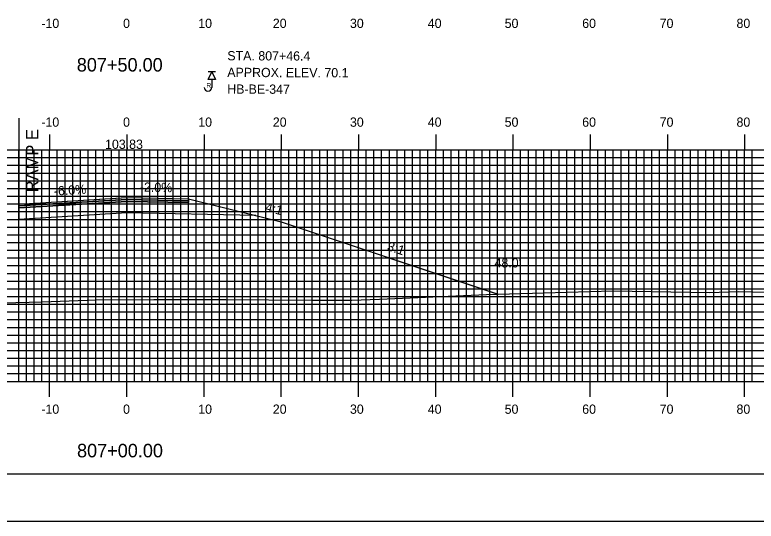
# Model space of a CAD drawing. Extents: x 1272 to 1616, y -1658 to -1438.
# Drawn here: x 1423.7 to 1519.7, y -1657.7 to -1592.1 of the extents above; entities that cross this region are included whole.
import ezdxf

# ---------------------------------------------------------------- set-up
doc = ezdxf.new("R2010")
doc.units = 0
for name, color, linetype in [('ANNOTATION', 7, 'Continuous'), ('BORDER', 7, 'Continuous'), ('BORING - REFUSAL', 7, 'Continuous'), ('D_Roadway_Centerline', 7, 'Continuous'), ('D_Roadway_Centerline_Text', 7, 'Continuous'), ('D_Roadway_Edge_Shoulder', 7, 'Continuous'), ('D_Roadway_Edge_TW', 7, 'Continuous'), ('D_Roadway_Pavement', 7, 'Continuous'), ('D_Roadway_SlopeLines', 7, 'Continuous'), ('D_Roadway_SubGrade', 7, 'Continuous'), ('D_Text_Standard', 7, 'Continuous'), ('H_V ANNOTATION', 7, 'Continuous'), ('MAJOR', 7, 'Continuous'), ('MINOR', 7, 'Continuous'), ('PLOT BOUNDARY', 7, 'Continuous'), ('S_Roadway_Centerline', 7, 'Continuous')]:
    doc.layers.add(name, color=color, linetype=linetype)

msp = doc.modelspace()

# ---------------------------------------------------------------- linework, layer by layer
at = {"layer": 'BORDER'}
msp.add_lwpolyline([(1288.561, -1651.604), (1608.561, -1651.604), (1608.561, -1441.604), (1288.561, -1441.604)], close=True, dxfattribs=at)
at = {"layer": 'BORING - REFUSAL'}
for p, q in [((1449.64, -1599.504), (1448.681, -1599.504)), ((1449.161, -1600.464), (1449.161, -1601.523))]:
    msp.add_line(p, q, dxfattribs=at)
msp.add_lwpolyline([(1449.161, -1599.504), (1449.64, -1600.464), (1448.681, -1600.464)], close=True, dxfattribs=at)
msp.add_arc((1448.675, -1601.523), 0.485, 180, 0, dxfattribs=at)
at = {"layer": 'D_Roadway_Centerline'}
msp.add_lwpolyline([(1424.161, -1616.617), (1424.161, -1616.617), (1438.139, -1615.779), (1438.161, -1615.777), (1446.149, -1615.937), (1446.161, -1615.937), (1454.843, -1618.108), (1454.856, -1618.111), (1454.861, -1618.112), (1458.161, -1618.937), (1486.206, -1628.286), (1486.25, -1628.3)], dxfattribs=at)
at = {"layer": 'D_Roadway_Edge_Shoulder'}
msp.add_lwpolyline([(1438.161, -1615.777), (1446.161, -1615.937), (1446.161, -1616.187), (1438.161, -1616.027)], close=True, dxfattribs=at)
at = {"layer": 'D_Roadway_Edge_TW'}
msp.add_lwpolyline([(1424.161, -1616.617), (1438.161, -1615.777), (1438.161, -1616.027), (1424.161, -1616.867)], close=True, dxfattribs=at)
at = {"layer": 'D_Roadway_Pavement'}
for points in [[(1424.161, -1616.867), (1438.161, -1616.027), (1438.161, -1616.277), (1424.161, -1617.117)], [(1438.161, -1616.027), (1446.161, -1616.187), (1446.161, -1616.437), (1438.161, -1616.277)]]:
    msp.add_lwpolyline(points, close=True, dxfattribs=at)
msp.add_lwpolyline([(1438.161, -1616.027), (1438.161, -1616.277)], dxfattribs=at)
msp.add_lwpolyline([(1438.161, -1616.027), (1438.161, -1616.277)], dxfattribs=at)
msp.add_lwpolyline([(1438.161, -1616.027), (1438.161, -1616.277)], dxfattribs=at)
at = {"layer": 'D_Roadway_SlopeLines'}
msp.add_lwpolyline([(1446.161, -1615.937), (1458.161, -1618.937), (1486.25, -1628.3)], dxfattribs=at)
msp.add_lwpolyline([(1446.161, -1615.937), (1458.161, -1618.937), (1486.25, -1628.3)], dxfattribs=at)
at = {"layer": 'D_Roadway_SubGrade'}
msp.add_line((1424.161, -1605.477), (1424.161, -1618.617), dxfattribs=at)
for points in [[(1424.161, -1617.117), (1438.161, -1616.277), (1438.161, -1617.777), (1424.161, -1618.617)], [(1438.161, -1616.277), (1438.161, -1616.027), (1446.161, -1616.187), (1446.161, -1615.937), (1454.856, -1618.111), (1438.161, -1617.777)], [(1438.161, -1616.277), (1446.161, -1616.437), (1446.161, -1616.187), (1446.161, -1615.937), (1454.856, -1618.111), (1438.161, -1617.777)]]:
    msp.add_lwpolyline(points, close=True, dxfattribs=at)
at = {"layer": 'MAJOR'}
for p, q in [((1428.161, -1607.6), (1428.161, -1609.604)), ((1438.161, -1607.6), (1438.161, -1609.604)), ((1448.161, -1607.6), (1448.161, -1609.604)), ((1458.161, -1607.6), (1458.161, -1609.604)), ((1468.161, -1607.6), (1468.161, -1609.604)), ((1478.161, -1607.6), (1478.161, -1609.604)), ((1488.161, -1607.6), (1488.161, -1609.604)), ((1498.161, -1607.6), (1498.161, -1609.604)), ((1508.161, -1607.6), (1508.161, -1609.604)), ((1518.161, -1607.6), (1518.161, -1609.604)), ((1298.161, -1609.604), (1578.161, -1609.604)), ((1298.161, -1609.604), (1578.161, -1609.604)), ((1428.161, -1639.604), (1428.161, -1609.604)), ((1438.161, -1639.604), (1438.161, -1609.604)), ((1448.161, -1639.604), (1448.161, -1609.604)), ((1458.161, -1639.604), (1458.161, -1609.604)), ((1468.161, -1639.604), (1468.161, -1609.604)), ((1478.161, -1639.604), (1478.161, -1609.604)), ((1488.161, -1639.604), (1488.161, -1609.604)), ((1498.161, -1639.604), (1498.161, -1609.604)), ((1508.161, -1639.604), (1508.161, -1609.604)), ((1518.161, -1639.604), (1518.161, -1609.604)), ((1298.161, -1614.604), (1578.161, -1614.604)), ((1298.161, -1619.604), (1578.161, -1619.604)), ((1298.161, -1624.604), (1578.161, -1624.604)), ((1298.161, -1629.604), (1578.161, -1629.604)), ((1298.161, -1634.604), (1578.161, -1634.604)), ((1298.161, -1639.604), (1578.161, -1639.604)), ((1298.161, -1639.604), (1578.161, -1639.604)), ((1428.161, -1641.608), (1428.161, -1639.604)), ((1438.161, -1641.608), (1438.161, -1639.604)), ((1448.161, -1641.608), (1448.161, -1639.604)), ((1458.161, -1641.608), (1458.161, -1639.604)), ((1468.161, -1641.608), (1468.161, -1639.604)), ((1478.161, -1641.608), (1478.161, -1639.604)), ((1488.161, -1641.608), (1488.161, -1639.604)), ((1498.161, -1641.608), (1498.161, -1639.604)), ((1508.161, -1641.608), (1508.161, -1639.604)), ((1518.161, -1641.608), (1518.161, -1639.604))]:
    msp.add_line(p, q, dxfattribs=at)
at = {"layer": 'MINOR'}
for p, q in [((1424.161, -1639.604), (1424.161, -1609.604)), ((1425.161, -1639.604), (1425.161, -1609.604)), ((1426.161, -1639.604), (1426.161, -1609.604)), ((1427.161, -1639.604), (1427.161, -1609.604)), ((1429.161, -1639.604), (1429.161, -1609.604)), ((1430.161, -1639.604), (1430.161, -1609.604)), ((1431.161, -1639.604), (1431.161, -1609.604)), ((1432.161, -1639.604), (1432.161, -1609.604)), ((1433.161, -1639.604), (1433.161, -1609.604)), ((1434.161, -1639.604), (1434.161, -1609.604)), ((1435.161, -1639.604), (1435.161, -1609.604)), ((1436.161, -1639.604), (1436.161, -1609.604)), ((1437.161, -1639.604), (1437.161, -1609.604)), ((1439.161, -1639.604), (1439.161, -1609.604)), ((1440.161, -1639.604), (1440.161, -1609.604)), ((1441.161, -1639.604), (1441.161, -1609.604)), ((1442.161, -1639.604), (1442.161, -1609.604)), ((1443.161, -1639.604), (1443.161, -1609.604)), ((1444.161, -1639.604), (1444.161, -1609.604)), ((1445.161, -1639.604), (1445.161, -1609.604)), ((1446.161, -1639.604), (1446.161, -1609.604)), ((1447.161, -1639.604), (1447.161, -1609.604)), ((1449.161, -1639.604), (1449.161, -1609.604)), ((1450.161, -1639.604), (1450.161, -1609.604)), ((1451.161, -1639.604), (1451.161, -1609.604)), ((1452.161, -1639.604), (1452.161, -1609.604)), ((1453.161, -1639.604), (1453.161, -1609.604)), ((1454.161, -1639.604), (1454.161, -1609.604)), ((1455.161, -1639.604), (1455.161, -1609.604)), ((1456.161, -1639.604), (1456.161, -1609.604)), ((1457.161, -1639.604), (1457.161, -1609.604)), ((1459.161, -1639.604), (1459.161, -1609.604)), ((1460.161, -1639.604), (1460.161, -1609.604)), ((1461.161, -1639.604), (1461.161, -1609.604)), ((1462.161, -1639.604), (1462.161, -1609.604)), ((1463.161, -1639.604), (1463.161, -1609.604)), ((1464.161, -1639.604), (1464.161, -1609.604)), ((1465.161, -1639.604), (1465.161, -1609.604)), ((1466.161, -1639.604), (1466.161, -1609.604)), ((1467.161, -1639.604), (1467.161, -1609.604)), ((1469.161, -1639.604), (1469.161, -1609.604)), ((1470.161, -1639.604), (1470.161, -1609.604)), ((1471.161, -1639.604), (1471.161, -1609.604)), ((1472.161, -1639.604), (1472.161, -1609.604)), ((1473.161, -1639.604), (1473.161, -1609.604)), ((1474.161, -1639.604), (1474.161, -1609.604)), ((1475.161, -1639.604), (1475.161, -1609.604)), ((1476.161, -1639.604), (1476.161, -1609.604)), ((1477.161, -1639.604), (1477.161, -1609.604)), ((1479.161, -1639.604), (1479.161, -1609.604)), ((1480.161, -1639.604), (1480.161, -1609.604)), ((1481.161, -1639.604), (1481.161, -1609.604)), ((1482.161, -1639.604), (1482.161, -1609.604)), ((1483.161, -1639.604), (1483.161, -1609.604)), ((1484.161, -1639.604), (1484.161, -1609.604)), ((1485.161, -1639.604), (1485.161, -1609.604)), ((1486.161, -1639.604), (1486.161, -1609.604)), ((1487.161, -1639.604), (1487.161, -1609.604)), ((1489.161, -1639.604), (1489.161, -1609.604)), ((1490.161, -1639.604), (1490.161, -1609.604)), ((1491.161, -1639.604), (1491.161, -1609.604)), ((1492.161, -1639.604), (1492.161, -1609.604)), ((1493.161, -1639.604), (1493.161, -1609.604)), ((1494.161, -1639.604), (1494.161, -1609.604)), ((1495.161, -1639.604), (1495.161, -1609.604)), ((1496.161, -1639.604), (1496.161, -1609.604)), ((1497.161, -1639.604), (1497.161, -1609.604)), ((1499.161, -1639.604), (1499.161, -1609.604)), ((1500.161, -1639.604), (1500.161, -1609.604)), ((1501.161, -1639.604), (1501.161, -1609.604)), ((1502.161, -1639.604), (1502.161, -1609.604)), ((1503.161, -1639.604), (1503.161, -1609.604)), ((1504.161, -1639.604), (1504.161, -1609.604)), ((1505.161, -1639.604), (1505.161, -1609.604)), ((1506.161, -1639.604), (1506.161, -1609.604)), ((1507.161, -1639.604), (1507.161, -1609.604)), ((1509.161, -1639.604), (1509.161, -1609.604)), ((1510.161, -1639.604), (1510.161, -1609.604)), ((1511.161, -1639.604), (1511.161, -1609.604)), ((1512.161, -1639.604), (1512.161, -1609.604)), ((1513.161, -1639.604), (1513.161, -1609.604)), ((1514.161, -1639.604), (1514.161, -1609.604)), ((1515.161, -1639.604), (1515.161, -1609.604)), ((1516.161, -1639.604), (1516.161, -1609.604)), ((1517.161, -1639.604), (1517.161, -1609.604)), ((1519.161, -1639.604), (1519.161, -1609.604)), ((1298.161, -1610.604), (1578.161, -1610.604)), ((1298.161, -1611.604), (1578.161, -1611.604)), ((1298.161, -1612.604), (1578.161, -1612.604)), ((1298.161, -1613.604), (1578.161, -1613.604)), ((1298.161, -1615.604), (1578.161, -1615.604)), ((1298.161, -1616.604), (1578.161, -1616.604)), ((1298.161, -1617.604), (1578.161, -1617.604)), ((1298.161, -1618.604), (1578.161, -1618.604)), ((1298.161, -1620.604), (1578.161, -1620.604)), ((1298.161, -1621.604), (1578.161, -1621.604)), ((1298.161, -1622.604), (1578.161, -1622.604)), ((1298.161, -1623.604), (1578.161, -1623.604)), ((1298.161, -1625.604), (1578.161, -1625.604)), ((1298.161, -1626.604), (1578.161, -1626.604)), ((1298.161, -1627.604), (1578.161, -1627.604)), ((1298.161, -1628.604), (1578.161, -1628.604)), ((1298.161, -1630.604), (1578.161, -1630.604)), ((1298.161, -1631.604), (1578.161, -1631.604)), ((1298.161, -1632.604), (1578.161, -1632.604)), ((1298.161, -1633.604), (1578.161, -1633.604)), ((1298.161, -1635.604), (1578.161, -1635.604)), ((1298.161, -1636.604), (1578.161, -1636.604)), ((1298.161, -1637.604), (1578.161, -1637.604)), ((1298.161, -1638.604), (1578.161, -1638.604))]:
    msp.add_line(p, q, dxfattribs=at)
at = {"layer": 'PLOT BOUNDARY'}
msp.add_lwpolyline([(1272.374, -1657.723), (1612.374, -1657.723), (1612.374, -1437.723), (1272.374, -1437.723)], close=True, dxfattribs=at)
at = {"layer": 'S_Roadway_Centerline'}
msp.add_lwpolyline([(1418.672, -1629.531), (1427.203, -1629.296), (1434.214, -1629.045), (1441.66, -1628.984), (1450.981, -1628.982), (1462.096, -1629.094), (1467.317, -1629.066), (1470.882, -1628.94), (1484.74, -1628.348), (1492.166, -1628.114), (1501.084, -1627.871), (1513.6, -1628.089), (1517.414, -1627.97), (1522.861, -1628.103), (1534.278, -1627.697), (1542.479, -1627.762), (1551.3, -1628.017), (1556.518, -1628.462), (1568.503, -1628.468), (1578.161, -1628.496)], dxfattribs=at)

# ---------------------------------------------------------------- texts
at = {"layer": 'ANNOTATION'}
for s, height, rotation, p in [('RAMP E', 1.6, 90, (1426.692, -1615.109)), ('-6.0%', 1.2, 3.43371, (1428.744, -1615.539)), ('-2.0%', 1.2, 358.85437, (1439.841, -1615.011)), ('4:1', 1.2, 345.96346, (1456.017, -1617.54)), ('3:1', 1.2, 341.56526, (1471.787, -1622.571))]:
    msp.add_text(s, height=height, rotation=rotation, dxfattribs=at).set_placement(p)
at = {"layer": 'BORING - REFUSAL'}
for s, p in [('STA. 807+46.4', (1451.178, -1597.997)), ('APPROX. ELEV. 70.1', (1451.171, -1600.157)), ('HB-BE-347', (1451.164, -1602.317))]:
    msp.add_text(s, height=1.2, rotation=359.81416, dxfattribs=at).set_placement(p)
msp.add_text('R', height=0.64, dxfattribs=at).set_placement((1448.452, -1601.579))
at = {"layer": 'D_Roadway_Centerline_Text'}
msp.add_text('103.83', height=1.2, dxfattribs=at).set_placement((1435.341, -1609.472))
at = {"layer": 'D_Text_Standard'}
msp.add_text("48.0'", height=1.2, dxfattribs=at).set_placement((1485.777, -1624.845))
at = {"layer": 'H_V ANNOTATION'}
for s, height, p in [('-10', 1.2, (1427.09, -1593.804)), ('0', 1.2, (1437.679, -1593.804)), ('10', 1.2, (1447.411, -1593.804)), ('20', 1.2, (1457.068, -1593.804)), ('30', 1.2, (1467.058, -1593.804)), ('40', 1.2, (1477.133, -1593.804)), ('50', 1.2, (1487.09, -1593.804)), ('60', 1.2, (1497.133, -1593.804)), ('70', 1.2, (1507.165, -1593.804)), ('80', 1.2, (1517.111, -1593.804)), ('807+50.00', 1.75, (1431.683, -1599.448)), ('-10', 1.2, (1427.09, -1606.604)), ('0', 1.2, (1437.679, -1606.604)), ('10', 1.2, (1447.411, -1606.604)), ('20', 1.2, (1457.068, -1606.604)), ('30', 1.2, (1467.058, -1606.604)), ('40', 1.2, (1477.133, -1606.604)), ('50', 1.2, (1487.09, -1606.604)), ('60', 1.2, (1497.133, -1606.604)), ('70', 1.2, (1507.165, -1606.604)), ('80', 1.2, (1517.111, -1606.604)), ('-10', 1.2, (1427.09, -1643.804)), ('0', 1.2, (1437.679, -1643.804)), ('10', 1.2, (1447.411, -1643.804)), ('20', 1.2, (1457.068, -1643.804)), ('30', 1.2, (1467.058, -1643.804)), ('40', 1.2, (1477.133, -1643.804)), ('50', 1.2, (1487.09, -1643.804)), ('60', 1.2, (1497.133, -1643.804)), ('70', 1.2, (1507.165, -1643.804)), ('80', 1.2, (1517.111, -1643.804)), ('807+00.00', 1.75, (1431.715, -1649.448))]:
    msp.add_text(s, height=height, dxfattribs=at).set_placement(p)

doc.saveas('drawing.dxf')
